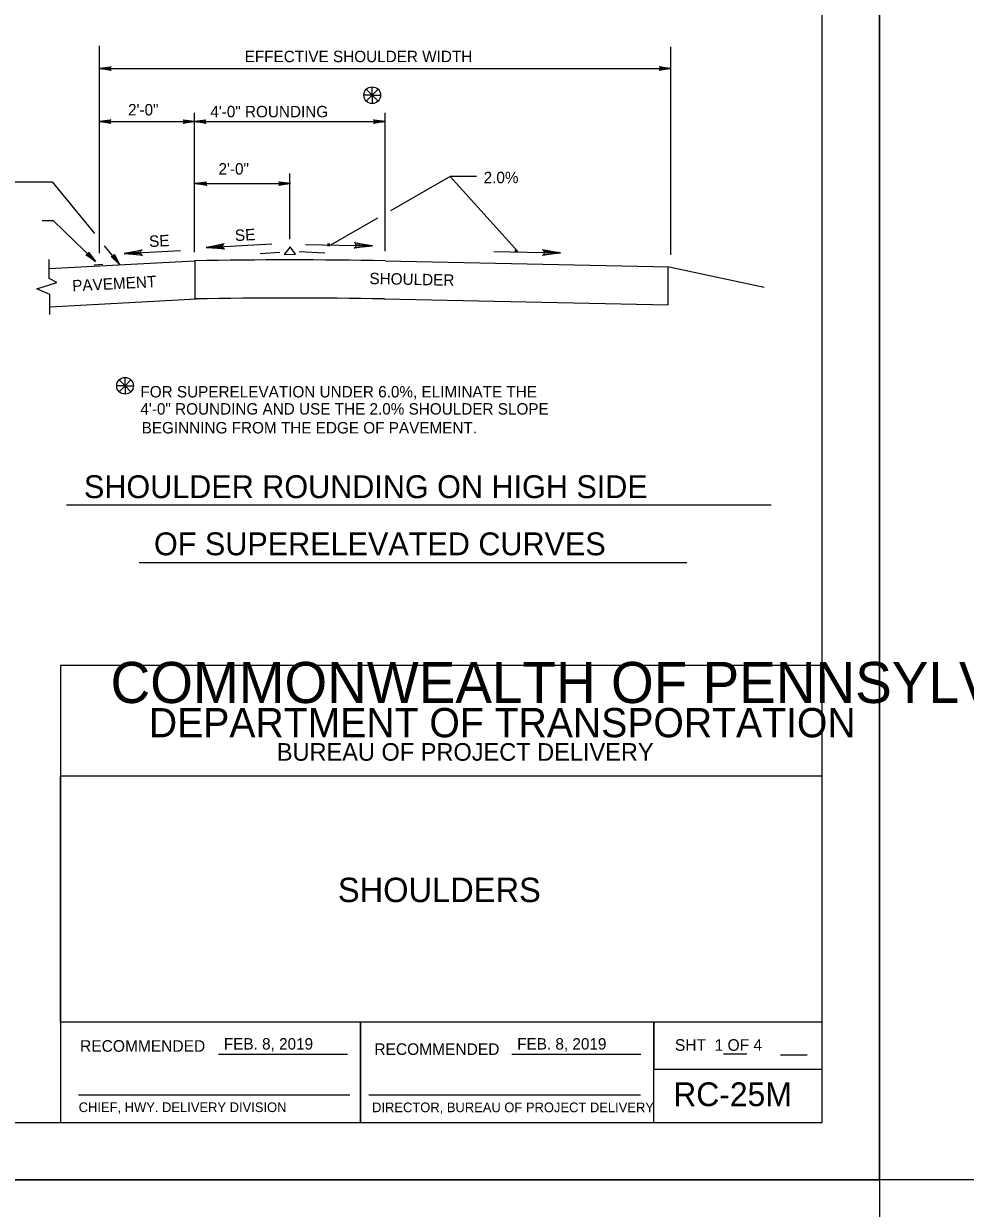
# Model space of a CAD drawing. Extents: x 638216 to 639962, y 297510 to 299292.
# Drawn here: x 638832.2 to 639079.4, y 298690.7 to 299001.7 of the extents above; entities that cross this region are included whole.
import ezdxf

# ---------------------------------------------------------------- set-up
doc = ezdxf.new("R2010")
doc.units = 0
for name, color, linetype in [('1', 7, 'Continuous'), ('2', 7, 'Continuous'), ('3', 7, 'Continuous'), ('PLT-BNDY', 7, 'Continuous')]:
    doc.layers.add(name, color=color, linetype=linetype)

msp = doc.modelspace()

# ---------------------------------------------------------------- linework, layer by layer
at = {"layer": '1'}
for p, q in [((638839.74, 298960.23), (638850.79, 298946.65)), ((638853.4, 298943.44), (638857.4, 298938.53)), ((638883.35, 298731.23), (638917.24, 298731.23)), ((638960.35, 298731.23), (638994.22, 298731.23)), ((639015.95, 298731.26), (639022.09, 298731.26)), ((639030.88, 298731.03), (639037.88, 298731.03)), ((638846.65, 298720.56), (638917.9, 298720.56)), ((638922.82, 298720.56), (638994.16, 298720.56))]:
    msp.add_line(p, q, dxfattribs=at)
msp.add_lwpolyline([(639041.88, 298713.24), (639041.88, 299277.24), (638255.88, 299277.24), (638255.88, 298713.24), (639041.88, 298713.24), (639041.88, 298739.6), (638841.88, 298739.6), (638841.88, 298804.28), (639041.88, 298804.28), (639041.88, 298833.24), (638841.88, 298833.24), (638841.88, 298713.24), (638920.69, 298713.24), (638920.69, 298739.6), (638920.69, 298713.24), (638997.69, 298713.24), (638997.69, 298739.6), (638997.69, 298727.28), (639041.88, 298727.28)], dxfattribs=at)
at = {"layer": '2'}
for p, q in [((638852.11, 298941.49), (638852.11, 298995.87)), ((639002.11, 298941), (639002.11, 298995.66)), ((638852.2, 298989.95), (639002.11, 298989.95)), ((638923.73, 298982.95), (638921.54, 298982.95)), ((638923.73, 298982.95), (638922.18, 298984.49)), ((638923.73, 298982.95), (638922.18, 298981.4)), ((638923.73, 298982.95), (638923.73, 298985.14)), ((638923.73, 298982.95), (638925.27, 298984.49)), ((638923.73, 298982.95), (638923.73, 298980.76)), ((638923.73, 298982.95), (638925.27, 298981.4)), ((638923.73, 298982.95), (638925.91, 298982.95)), ((638877.11, 298941.76), (638877.11, 298978.35)), ((638927.11, 298942.03), (638927.11, 298978.35)), ((638852.11, 298976.02), (638877.09, 298976.02)), ((638877.09, 298976.02), (638927.11, 298976.02)), ((638902.1, 298945.11), (638902.1, 298962.35)), ((638944.17, 298961.59), (638928.54, 298952.62)), ((638951.12, 298961.59), (638944.17, 298961.59)), ((638944.17, 298961.59), (638961.98, 298941.89)), ((638819.12, 298960.23), (638839.74, 298960.23)), ((638877.27, 298959.76), (638902.24, 298959.76)), ((638837.08, 298950.04), (638839.96, 298950.04)), ((638839.96, 298950.04), (638851.07, 298939.28)), ((638925.08, 298950.63), (638912.78, 298943.58)), ((638858.62, 298941.37), (638873.41, 298942.16)), ((638880.13, 298943), (638897.39, 298943.92)), ((638906.26, 298943.78), (638923.81, 298943.41)), ((638838.94, 298934.84), (638838.94, 298939.77)), ((638838.94, 298937.44), (638877.11, 298939.47)), ((638877.29, 298929.47), (638877.29, 298939.47)), ((638899.45, 298941.69), (638894.29, 298941.28)), ((638904.58, 298941.91), (638911.29, 298941.55)), ((638927.11, 298939.47), (639001.66, 298937.9)), ((638955.64, 298941.93), (638973.2, 298941.56)), ((638850.75, 298938.44), (638853, 298938.6)), ((639001.45, 298927.91), (639001.45, 298937.91)), ((639001.66, 298937.9), (639026.58, 298932.54)), ((638839.08, 298925.4), (638839.08, 298930.6)), ((638839.08, 298927.43), (638877.64, 298929.49)), ((638926.9, 298929.47), (639001.45, 298927.91)), ((638858.84, 298906.66), (638857.29, 298908.21)), ((638858.84, 298906.66), (638858.84, 298908.85)), ((638858.84, 298906.66), (638860.38, 298908.21)), ((638858.84, 298906.66), (638856.65, 298906.66)), ((638858.84, 298906.66), (638857.29, 298905.11)), ((638858.84, 298906.66), (638858.84, 298904.47)), ((638858.84, 298906.66), (638860.38, 298905.11)), ((638858.84, 298906.66), (638861.03, 298906.66)), ((638843.5, 298875.41), (639028.49, 298875.41)), ((638862.59, 298860.3), (639006.35, 298860.3))]:
    msp.add_line(p, q, dxfattribs=at)
for points in [[(638855.06, 298989.59), (638854.95, 298989.8), (638852.2, 298989.95), (638855.06, 298989.59), (638855.2, 298989.47), (638852.2, 298989.95), (638854.95, 298990.09), (638855.05, 298990.29), (638852.2, 298989.95), (638855.2, 298990.43), (638855.05, 298990.29)], [(638999.26, 298990.31), (638999.36, 298990.1), (639002.11, 298989.95), (638999.26, 298990.31), (638999.11, 298990.44), (639002.11, 298989.95), (638999.36, 298989.82), (638999.26, 298989.61), (639002.11, 298989.95), (638999.11, 298989.47), (638999.26, 298989.61)], [(638854.96, 298975.66), (638854.86, 298975.86), (638852.11, 298976.02), (638854.96, 298975.66), (638855.11, 298975.53), (638852.11, 298976.02), (638854.86, 298976.15), (638854.96, 298976.36), (638852.11, 298976.02), (638855.11, 298976.49), (638854.96, 298976.36)], [(638874.23, 298976.38), (638874.34, 298976.17), (638877.09, 298976.02), (638874.23, 298976.38), (638874.09, 298976.5), (638877.09, 298976.02), (638874.34, 298975.88), (638874.24, 298975.68), (638877.09, 298976.02), (638874.09, 298975.54), (638874.24, 298975.68)], [(638879.94, 298975.66), (638879.83, 298975.86), (638877.09, 298976.02), (638879.94, 298975.66), (638880.09, 298975.53), (638877.09, 298976.02), (638879.83, 298976.15), (638879.93, 298976.36), (638877.09, 298976.02), (638880.09, 298976.49), (638879.93, 298976.36)], [(638924.26, 298976.38), (638924.36, 298976.17), (638927.11, 298976.02), (638924.26, 298976.38), (638924.11, 298976.5), (638927.11, 298976.02), (638924.36, 298975.88), (638924.26, 298975.68), (638927.11, 298976.02), (638924.11, 298975.54), (638924.26, 298975.68)], [(638880.12, 298959.4), (638880.01, 298959.61), (638877.27, 298959.76), (638880.12, 298959.4), (638880.27, 298959.27), (638877.27, 298959.76), (638880.01, 298959.89), (638880.11, 298960.1), (638877.27, 298959.76), (638880.27, 298960.23), (638880.11, 298960.1)], [(638899.39, 298960.11), (638899.5, 298959.91), (638902.24, 298959.76), (638899.39, 298960.11), (638899.24, 298960.24), (638902.24, 298959.76), (638899.5, 298959.62), (638899.4, 298959.42), (638902.24, 298959.76), (638899.24, 298959.28), (638899.4, 298959.42)], [(638899.39, 298960.11), (638899.5, 298959.91), (638902.24, 298959.76), (638899.39, 298960.11), (638899.24, 298960.24), (638902.24, 298959.76), (638899.5, 298959.62), (638899.4, 298959.42), (638902.24, 298959.76), (638899.24, 298959.28), (638899.4, 298959.42)], [(638863.18, 298941.04), (638863, 298941.36), (638858.62, 298941.37), (638863.18, 298941.04), (638863.43, 298940.86), (638858.62, 298941.37), (638862.97, 298941.82), (638863.11, 298942.15), (638858.62, 298941.37), (638863.34, 298942.38), (638863.11, 298942.15)], [(638884.7, 298942.67), (638884.51, 298942.99), (638880.13, 298943), (638884.7, 298942.67), (638884.94, 298942.49), (638880.13, 298943), (638884.48, 298943.45), (638884.62, 298943.78), (638880.13, 298943), (638884.86, 298944.01), (638884.62, 298943.78)], [(638919.28, 298944.07), (638919.45, 298943.74), (638923.81, 298943.41), (638919.28, 298944.07), (638919.05, 298944.28), (638923.81, 298943.41), (638919.44, 298943.28), (638919.27, 298942.96), (638923.81, 298943.41), (638919.02, 298942.75), (638919.27, 298942.96)], [(638968.67, 298942.22), (638968.83, 298941.89), (638973.2, 298941.56), (638968.67, 298942.22), (638968.44, 298942.43), (638973.2, 298941.56), (638968.83, 298941.44), (638968.66, 298941.11), (638973.2, 298941.56), (638968.41, 298940.9), (638968.66, 298941.11)], [(638849.27, 298941.52), (638849.2, 298941.3), (638851.07, 298939.28), (638849.27, 298941.52), (638849.25, 298941.71), (638851.07, 298939.28), (638849, 298941.09), (638848.79, 298941.01), (638851.07, 298939.28), (638848.59, 298941.02), (638848.79, 298941.01)], [(638855.94, 298941.01), (638855.84, 298940.8), (638857.4, 298938.53), (638855.94, 298941.01), (638855.95, 298941.2), (638857.4, 298938.53), (638855.61, 298940.62), (638855.39, 298940.57), (638857.4, 298938.53), (638855.19, 298940.61), (638855.39, 298940.57)], [(638839.08, 298930.6), (638835.71, 298932.07), (638840.91, 298933.81), (638838.94, 298934.84)]]:
    msp.add_lwpolyline(points, dxfattribs=at)
msp.add_lwpolyline([(638902.16, 298943.13), (638900.64, 298941.12), (638903.58, 298941.17)], close=True, dxfattribs=at)
for centre in [(638923.73, 298982.95), (638858.84, 298906.66)]:
    msp.add_circle(centre, 2.19, dxfattribs=at)
for radius in [1389.12, 1379.12]:
    msp.add_arc((638902.11, 297550.58), radius, 88.96879, 91.03121, dxfattribs=at)
at = {"layer": 'PLT-BNDY'}
for points in [[(638215.88, 299292.24), (639056.88, 299292.24), (639056.88, 298698.24), (638215.88, 298698.24)], [(639056.88, 299292.24), (639897.88, 299292.24), (639897.88, 298698.24), (639056.88, 298698.24)], [(638215.88, 298698.24), (639056.88, 298698.24), (639056.88, 298104.24), (638215.88, 298104.24)]]:
    msp.add_lwpolyline(points, close=True, dxfattribs=at)

# ---------------------------------------------------------------- texts
at = {"layer": '1'}
for s, height, p in [('2\'-0"', 3, (638859.64, 298977.63)), ('2\'-0"', 3, (638883.38, 298962.11)), ('COMMONWEALTH OF PENNSYLVANIA', 10.7834, (638855.04, 298823.38)), ('DEPARTMENT OF TRANSPORTATION', 7.6843, (638865.1, 298814.39)), ('BUREAU OF PROJECT DELIVERY', 4.6221, (638898.69, 298808.23)), ('SHOULDERS', 6.4, (638914.72, 298771.13)), ('RECOMMENDED', 3.048, (638847.05, 298731.83)), ('FEB. 8, 2019', 3, (638884.79, 298732.41)), ('RECOMMENDED', 3.048, (638924.29, 298731)), ('FEB. 8, 2019', 3, (638961.79, 298732.41)), ('SHT  1 OF 4', 3.048, (639003.2, 298732.09)), ('APPROVED', 0.0192, (638884.91, 298731.17)), ('RC-25M', 6.25, (639002.76, 298717.55)), ('CHIEF, HWY. DELIVERY DIVISION', 2.54, (638846.68, 298716)), ('DIRECTOR, BUREAU OF PROJECT DELIVERY', 2.54, (638923.7, 298715.97))]:
    msp.add_text(s, height=height, dxfattribs=at).set_placement(p)
at = {"layer": '2'}
for p in [(638913.25, 298944.06), (638962.39, 298942.39)]:
    msp.add_text('.', height=5.07, rotation=180, dxfattribs=at).set_placement(p)
at = {"layer": '3'}
for s, height, p in [('EFFECTIVE SHOULDER WIDTH', 3, (638890.26, 298991.62)), ('4\'-0" ROUNDING', 3, (638881.23, 298977.14)), ('2.0%', 3, (638952.99, 298959.84)), ('FOR SUPERELEVATION UNDER 6.0%, ELIMINATE THE', 3, (638862.88, 298903.6)), ('4\'-0" ROUNDING AND USE THE 2.0% SHOULDER SLOPE', 3, (638862.88, 298899.1)), ('BEGINNING FROM THE EDGE OF PAVEMENT.', 3, (638863.21, 298894.15)), ('SHOULDER ROUNDING ON HIGH SIDE', 6, (638848.06, 298877.17)), ('OF SUPERELEVATED CURVES', 6, (638866.44, 298862.17))]:
    msp.add_text(s, height=height, dxfattribs=at).set_placement(p)
for s, rotation, p in [('SE', 3.0514, (638865.24, 298943.06)), ('SE', 3.0514, (638887.77, 298944.63)), ('SHOULDER', 358.7945, (638922.98, 298933.36)), ('PAVEMENT', 3.0517, (638845.06, 298931.41))]:
    msp.add_text(s, height=3, rotation=rotation, dxfattribs=at).set_placement(p)

doc.saveas('drawing.dxf')
